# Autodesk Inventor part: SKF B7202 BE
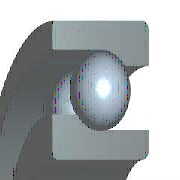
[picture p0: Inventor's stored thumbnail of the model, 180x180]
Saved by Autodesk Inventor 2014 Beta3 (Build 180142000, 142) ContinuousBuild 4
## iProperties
Created: 2010-02
Part Number: SKF B7202 BE
Material: Steel, Mild
Description: Single row angular contact ball bearings SKF
Document SubType Name: Modeling
Standard: SKF B
Designer: Thom Tremblay
Language: en-US
Size Designation: SKF B7202 BE
Categories: <MemberInstance><Categories><Category DisplayName="Shaft Parts" InternalName="7f7aeb1f-a693-4053-b835-cee3144e0d98" Mnemonic="SHFT"><Category DisplayName="Beari
Density: 7.86 g/cm^3
Appearance: Steel
IsCustomPart: 0
Author: Thom Tremblay
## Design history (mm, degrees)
node "WorkPlane1"
workplane "Work Plane2"
node "WorkPlane2"
node "Sketch1"
node "WorkPoint1"
node "Sketch2"
node "WorkPoint3"
node "Sketch3"
node "WorkPoint2"
node "WorkAxis1"
node "Sketch7"
workaxis "Work Axis2"
pattern_circular "PolarArray1" dims angle "d18" = 360 deg
fillet "Fillet1" dims "d19" = 0.3 (= r1)
fillet "Fillet2" dims "d20" = 0.6 (= r)
body "Solid1"
revolve "Revolution1" stored, may be unused: angle "d7" = 360 deg
revolve "Revolution2" stored, may be unused: angle "d12" = 360 deg
revolve "Revolution3" stored, may be unused: angle "d15" = 360 deg
sketch "Sketch4"
  geometry: L1 (17.5, 0)-(7.5, 0); L2 (17.5, 11)-(17.5, 0); L3 (7.5, 11)-(17.5, 11); L4 (7.5, 0)-(7.5, 11); L5 (0, -3.737)-(0, 15.931); L6 (0, -3.737)-(0, 15.931); L7 (0, -7.671)-(0, 19.865) reference; L8 (-4.7, 0)-(28.2, 0) reference
  constraints: 12 end point, 3 vertical, 2 collinear, 2 horizontal
  dimensions: "d2" = 7.5 horizontal distance of L3.start L5.end (= 0.5 x Diam); "d4" = 17.5 horizontal distance of L2.start L5.end (= 0.5 x DD); "d6" = 11 distance of L1.end L3.start (= B)
sketch "Sketch5"
  geometry: L1 (15.5, 11)-(10.7, 11); L2 (15.5, 5.5)-(15.5, 11); L3 (14.3, 0)-(14.3, 3.1); L4 (9.5, 0)-(14.3, 0); L5 (9.5, 5.5)-(9.5, 0); L6 (10.7, 11)-(10.7, 7.9); L7 (17.5, 0)-(-17.5, 0) reference; L8 (17.5, 11)-(-17.5, 11) reference; L9 (0, 40.963)-(0, -26.963); L10 (0, -40.549)-(0, 54.549) reference; A1 r 3 centre (12.5, 5.5) between (14.3, 3.1) and (15.5, 5.5); A2 r 3 centre (12.5, 5.5) between (10.7, 7.9) and (9.5, 5.5); A3 r 3 centre (12.5, 5.5) between (15.5, 5.5) and (10.7, 7.9)
  constraints: 14 end point, 7 point on circle, 4 vertical, 3 centre point, 3 collinear, 2 horizontal, 2 tangent, 1 coincident, 1 concentric
  dimensions: "d9" = 5.5 vertical distance of A2.centre L3.start (= 0.5 x B); "d11" = 6 diameter of A3 (= msp_mdtdk); "d21" = 25 diameter of A1.centre L9 (= msp_mdtds); "d22" = 21.4 diameter of L6 L9 (= msp_md); "d23" = 28.6 diameter of L3 L9 (= msp_vd)
sketch "Sketch6"
  geometry: L1 (12.5, 2.5)-(12.5, 8.5); L2 (12.5, 13.675)-(12.5, -2.513); L3 (17.5, 0)-(-17.5, 0) reference; L4 (12.5, 13.675)-(12.5, -2.513); L5 (15.5, 5.5)-(-15.5, 5.5) reference; A1 r 3 centre (12.5, 5.5) between (12.5, 2.5) and (12.5, 8.5); A2 r 3 centre (12.5, 5.5) between (10.7, 7.9) and (9.5, 5.5) reference
  constraints: 6 end point, 4 point on line, 2 point on circle, 1 centre point, 1 concentric, 1 vertical
  dimensions: "d14" = 3 radius of A1 (= 0.5 x msp_mdtdk)
other parameters: "Diam" = 15 [user parameter; used in 3 equation terms], "DD" = 35 [user parameter; used in 3 equation terms], "B" = 11 [user parameter; used in 3 equation terms], "r" = 0.6 [user parameter; used in 1 equation term], "msp_mdtdk" = 6 (= -0.3 x Diam + 0.3 x DD) [user parameter; used in 5 equation terms], "msp_mdtds" = 25 (= 0.5 x DD + 0.5 x Diam) [user parameter; used in 4 equation terms], "msp_md" = 21.4 (= msp_mdtds - 0.6 x msp_mdtdk) [user parameter; used in 1 equation term], "msp_vd" = 28.6 (= msp_mdtds + 0.6 x msp_mdtdk) [user parameter; used in 1 equation term], "r1" = 0.3 [user parameter; used in 1 equation term], "d0" = -11 (computed from B), "d3" = 23.5 (derived), "d5" = 14 (derived), "d8" = 7 (derived), "d10" = 8.1 (derived), "d13" = 4.05 (derived), "d26" = 0, "d27" = 0, "d28" = 0, "d29" = 0, "d30" = 0
